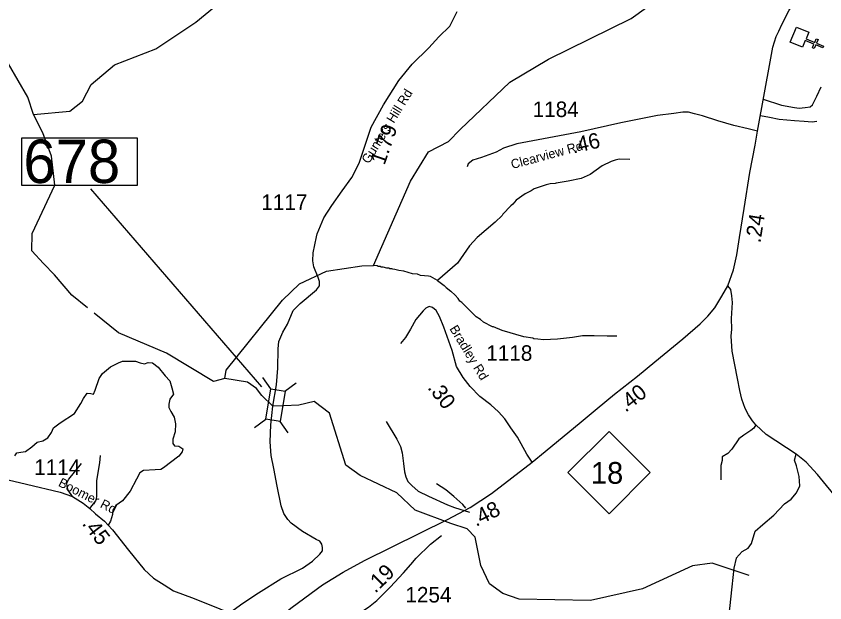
# Model space of a CAD drawing. Extents: x 1248224 to 1454986, y 825081 to 985870.
# Drawn here: x 1331629 to 1338152, y 851342 to 856073 of the extents above; entities that cross this region are included whole.
import ezdxf

# ---------------------------------------------------------------- set-up
doc = ezdxf.new("R2010")
doc.units = 0
for name, color, linetype in [('Exist Cultural Church CELL', 7, 'Continuous'), ('Exist Hydrographic Creek Single Shore', 7, 'Continuous'), ('Exist Hydrographic Misc Water Feature', 7, 'Continuous'), ('Exist Road Non-System Type 51', 7, 'Continuous'), ('Exist Road Primary NC Attributed', 7, 'Continuous'), ('Exist Road Primary NC Mileage Hundredths English Label', 7, 'Continuous'), ('Exist Road Primary NC Shield CELL', 7, 'Continuous'), ('Exist Road Primary NC Shield Number Label', 7, 'Continuous'), ('Exist Road Secondary Mileage Hundredths English Label', 7, 'Continuous'), ('Exist Road Secondary Structure Standard Bridge CELL', 7, 'Continuous'), ('Exist Road Secondary Structure Standard Bridge Number Label', 7, 'Continuous'), ('Exist Road Secondary Type 41 Attributed', 7, 'Continuous'), ('Exist Road Secondary Type 51 Attributed', 7, 'Continuous'), ('Exist Road Secondary Type 51 Label', 7, 'Continuous'), ('Exist Road Secondary Type 51 Number Label', 7, 'Continuous')]:
    doc.layers.add(name, color=color, linetype=linetype)

msp = doc.modelspace()

# ---------------------------------------------------------------- linework, layer by layer
at = {"layer": 'Exist Cultural Church CELL'}
msp.add_lwpolyline([(1338022.6, 855943.8), (1338000.8, 855891.2), (1338071, 855861.8), (1338083.3, 855891.3), (1338098.1, 855885.2), (1338085.7, 855855.7), (1338141.2, 855832.4), (1338135, 855817.7), (1338079.5, 855840.9), (1338067.2, 855811.4), (1338052.5, 855817.5), (1338064.8, 855847), (1337994.6, 855876.4), (1337972.2, 855823.3), (1337874, 855864.4), (1337924.4, 855984.9)], close=True, dxfattribs=at)
at = {"layer": 'Exist Hydrographic Creek Single Shore'}
for points in [[(1333312.1, 853152.1), (1333220, 853127.7), (1332842, 853355.3), (1332454.1, 853520.6), (1332257.2, 853678.9)], [(1333699.8, 852927.7), (1333612.1, 853015.1), (1333569, 853071.4), (1333495.1, 853122.2), (1333312.1, 853152.1)], [(1334034.1, 852966.9), (1333908.1, 852936.6), (1333787.3, 852929.5), (1333699.8, 852927.7)]]:
    msp.add_lwpolyline(points, dxfattribs=at)
at = {"layer": 'Exist Hydrographic Misc Water Feature'}
for points in [[(1331769, 855280.8), (1332062, 855307.7), (1332164, 855387.8), (1332234, 855521), (1332421.1, 855681.4), (1332757, 855809.2), (1333079.1, 856026), (1333334.1, 856237.4), (1333699, 856479.6), (1333857.5, 856585.9), (1333920.1, 856672.1), (1334330, 857438.7), (1334527, 857661.3), (1334901.1, 857991.8), (1335274, 858266.6)], [(1335210.1, 855159.1), (1335612.1, 855541.7), (1335924.1, 855725.8), (1336590.1, 856053.9), (1337048.1, 856386.1), (1337380.1, 856694.5), (1337689, 857473), (1338136.1, 858071.3)], [(1331769, 855280.8), (1331722.3, 855420.3), (1331566.9, 855689), (1331377.3, 855811.9)], [(1332203.5, 853722.1), (1332077.1, 853823.6), (1331938.3, 853987.8), (1331850.1, 854077.7), (1331755.2, 854180.2), (1331757.1, 854319.4), (1331941.8, 854710.4), (1331914.3, 854943), (1331845, 855132.7), (1331769, 855280.8)], [(1333312.1, 853152.1), (1333322.1, 853217.6), (1333778.1, 853782.9), (1333914, 853914.7), (1334133, 854015.4), (1334418.1, 854058.9), (1334512.2, 854061.4), (1334809.1, 854743.7), (1334956.1, 854980.4), (1335117.1, 855062.6), (1335210.1, 855159.1)], [(1336579.7, 854917.1), (1336493.1, 854919.4), (1336461, 854912.2), (1336428.7, 854901), (1336356, 854866.7), (1336258.3, 854797.1), (1336185.6, 854762.8), (1336081, 854741.3), (1335984.7, 854727.6), (1335976.6, 854723.8), (1335936.5, 854720.8), (1335904.3, 854713.5), (1335807.5, 854679.8), (1335783.2, 854664.4), (1335734.6, 854641.6), (1335661.4, 854589.3), (1335636.7, 854557.9), (1335620.4, 854544.3), (1335554.9, 854475.9), (1335548.7, 854466), (1335493.4, 854411.3), (1335346.9, 854288.2), (1335285.8, 854221.9), (1335189, 854080.6), (1335028.4, 853941.4)], [(1335028.4, 853941.4), (1334970.8, 853972.8), (1334954.9, 853977.1), (1334891.1, 853982.7), (1334867.2, 853991.2), (1334827.3, 853996.1), (1334755.8, 854017.8), (1334715.9, 854022.8), (1334684.2, 854031.5), (1334668.2, 854031.9), (1334660.2, 854036), (1334644.2, 854036.4), (1334636.3, 854040.6), (1334620.3, 854041), (1334588.5, 854049.7), (1334572.5, 854050.1), (1334564.6, 854054.3), (1334548.6, 854054.7), (1334540.7, 854058.8), (1334512.2, 854061.4)], [(1335028.4, 853941.4), (1335081.1, 853900.2), (1335096.8, 853883.8), (1335136.2, 853854.9), (1335169.8, 853821.9)], [(1336474.8, 853492.1), (1336396.8, 853492), (1336290.8, 853496.5), (1336196.8, 853494.7), (1336116.5, 853480.6), (1335996.2, 853467.5), (1335884, 853464.2), (1335836.1, 853467.3), (1335804.2, 853472.1), (1335796.3, 853476.2), (1335724.5, 853486), (1335549.7, 853538.1), (1335478.3, 853567.8), (1335470.3, 853568), (1335399.2, 853605.7), (1335375.6, 853626.2), (1335340.1, 853649.1), (1335316.6, 853671.6), (1335285.5, 853700.9), (1335281.6, 853707.9), (1335223.6, 853763.6), (1335208, 853775.9), (1335194.5, 853796.5), (1335169.8, 853821.9)], [(1335136.2, 851982.8), (1334847.1, 852090.5), (1334700.1, 852228), (1334403.1, 852368.5), (1334289.1, 852452.9), (1334157.1, 852872.5), (1334034.1, 852966.9)], [(1337542.1, 851563.6), (1337244.2, 851661.5), (1337085.2, 851641.7), (1336681.1, 851456.2), (1336262.2, 851359.5), (1335687.1, 851371.1), (1335554.1, 851416.4), (1335448.1, 851494.1), (1335376.2, 851643.2), (1335331.2, 851870.7), (1335266.2, 851937.6), (1335136.2, 851982.8)]]:
    msp.add_lwpolyline(points, dxfattribs=at)
at = {"layer": 'Exist Road Non-System Type 51'}
for points in [[(1337655.9, 855404), (1337802.4, 855354.1), (1337906.6, 855337.5), (1337944.3, 855330), (1337992.6, 855336), (1338034.9, 855342.1), (1338053, 855358.7), (1338065.1, 855384.4), (1338089.2, 855426.7), (1338122.5, 855502.2)], [(1337633.3, 855272.6), (1337705.8, 855259), (1337784.3, 855243.8), (1337906.6, 855231.8), (1337985.1, 855227.2), (1338050, 855221.2), (1338089.2, 855225.7)], [(1334912.5, 853696.4), (1334853.4, 853625.6), (1334810, 853549.6), (1334768.5, 853482.7), (1334730.5, 853432.1)], [(1331619.5, 852528.8), (1331635.5, 852550.8), (1331667.5, 852556.8), (1331705.4, 852562.8), (1331755.3, 852600.7), (1331797.3, 852636.7), (1331843.2, 852648.7), (1331885.1, 852672.7), (1331913.1, 852716.6), (1331929.1, 852752.6), (1331985, 852792.6), (1332098.8, 852868.5), (1332150.7, 852950.4), (1332172.7, 852990.4), (1332202.6, 853032.4), (1332232.6, 853030.4), (1332252.6, 853024.4), (1332266.5, 853056.4), (1332298.5, 853152.3), (1332324.4, 853190.2), (1332390.3, 853244.2), (1332454.2, 853278.2), (1332488.2, 853290.2), (1332538.1, 853292.2), (1332592, 853290.2), (1332630, 853276.2), (1332663.9, 853268.2), (1332693.9, 853280.2), (1332729.8, 853278.2), (1332775.8, 853242.2), (1332831.7, 853172.3), (1332867.6, 853132.3), (1332883.6, 853076.3), (1332899.6, 853024.4), (1332867.6, 852984.4), (1332861.6, 852944.4), (1332861.6, 852918.5), (1332875.6, 852884.5), (1332903.6, 852840.5), (1332913.5, 852786.6), (1332911.5, 852720.6), (1332893.6, 852660.7), (1332891.6, 852626.7), (1332905.6, 852608.7), (1332941.5, 852604.7), (1332973.4, 852584.7), (1332967.5, 852558.8), (1332941.5, 852524.8), (1332817.7, 852430.9), (1332795.7, 852416.9), (1332749.8, 852414.9), (1332655.9, 852408.9), (1332625.9, 852389.7), (1332599.9, 852339.8), (1332548, 852243.8), (1332486.1, 852163.9), (1332434.2, 852125.9), (1332410.2, 852090), (1332406.2, 852054), (1332390.3, 852000), (1332372.3, 851968.1)], [(1334612.9, 852804.5), (1334700.7, 852662.6), (1334728.7, 852602.7), (1334742.7, 852550.7), (1334754.6, 852466.8), (1334762.6, 852398.8), (1334772.6, 852356.9), (1334788.6, 852320.9), (1334820.5, 852286.9), (1334872.5, 852242.9), (1334954.3, 852201), (1335108.1, 852131), (1335164, 852111.1), (1335285.3, 852071.9)], [(1337594.6, 852776.9), (1337579.5, 852750.9), (1337556.5, 852733.1), (1337498, 852694.9), (1337459.8, 852664.3), (1337401.3, 852580.3), (1337370.7, 852547.2), (1337324.9, 852519.1), (1337324.9, 852491.1), (1337314.8, 852450.4), (1337314.8, 852333.2)], [(1332222.4, 852103.8), (1332272.4, 852165.8), (1332280.4, 852195.7), (1332280.4, 852245.7), (1332280.4, 852327.6), (1332304.3, 852471.5), (1332310.3, 852531.5)], [(1337436, 851702.7), (1337486.1, 851756.1), (1337532.8, 851782.9), (1337559.5, 851819.6), (1337589.6, 851919.9), (1337653, 851973.3), (1337739.8, 852050.2), (1337826.6, 852140.4), (1337879.8, 852179.3), (1337923.2, 852229.4), (1337949.9, 852286.2), (1337946.6, 852359.7), (1337923.2, 852446.6), (1337906.5, 852493.4), (1337920.1, 852541.9)], [(1332084, 852198.6), (1332048.7, 852249.7), (1332040.7, 852277.7), (1332038.7, 852309.6), (1332052.7, 852339.6), (1332156.6, 852465.5)], [(1335256.7, 852104.6), (1335232.7, 852133.9), (1335160.8, 852199.2), (1335095.6, 852253.8), (1335021, 852301.8)], [(1337436, 851702.7), (1337419.3, 851622.5), (1337402.6, 851472.1), (1337382.6, 851295.1), (1337332.5, 850910.8)]]:
    msp.add_lwpolyline(points, dxfattribs=at)
at = {"layer": 'Exist Road Primary NC Attributed'}
for points in [[(1337610, 855145.1), (1337716.5, 855735.7), (1337733.8, 855822.1), (1337760, 855908.7), (1337780.9, 855952.3), (1337805, 856006), (1337865.7, 856120.5), (1338104.6, 856447.9), (1338581.5, 857121), (1338962.1, 857639.4), (1339074.1, 857803.7), (1339252.1, 858033.9), (1339325.6, 858141.9), (1339512.6, 858365.5)], [(1337370.6, 853897.2), (1337415.9, 854026.8), (1337441.8, 854147.1), (1337463.9, 854288.9), (1337500.9, 854522.2), (1337547.1, 854811.2), (1337591.5, 855031.6), (1337610, 855145.1)], [(1335790.6, 852477.7), (1335895.8, 852561.6), (1336187.6, 852801.6), (1336315.3, 852909), (1336455.9, 853025.7), (1336641, 853170.2), (1336780.9, 853284.3), (1337006.7, 853471.3), (1337147.3, 853591.7), (1337208.4, 853652.8), (1337265.7, 853721.3), (1337321.3, 853813.9), (1337370.6, 853897.2)], [(1333651.5, 851145.2), (1333855.1, 851307.7), (1334101.2, 851487.6), (1334267.2, 851589.2), (1334439.1, 851683.1), (1335108.2, 852014.5), (1335292.7, 852111.3), (1335462.9, 852222.4), (1335790.6, 852477.7)]]:
    msp.add_lwpolyline(points, dxfattribs=at)
at = {"layer": 'Exist Road Primary NC Shield CELL'}
msp.add_lwpolyline([(1336078.6, 852392), (1336411.6, 852725), (1336744.6, 852392), (1336411.6, 852059)], close=True, dxfattribs=at)
at = {"layer": 'Exist Road Secondary Structure Standard Bridge CELL'}
for p, q in [((1333684.1, 853067.4), (1333618, 853159.2)), ((1333795.9, 853049.2), (1333887.7, 853115.4)), ((1333552, 852756.7), (1333643.8, 852822.8)), ((1333824.3, 852712.4), (1333758.1, 852804.2))]:
    msp.add_line(p, q, dxfattribs=at)
msp.add_lwpolyline([(1333643.8, 852822.8), (1333683.6, 853067.5), (1333797.9, 853048.9), (1333758.1, 852804.2)], close=True, dxfattribs=at)
at = {"layer": 'Exist Road Secondary Structure Standard Bridge Number Label'}
msp.add_line((1333611, 853083.1), (1332230.3, 854681.8), dxfattribs=at)
msp.add_lwpolyline([(1331674.9, 855091.9), (1332603.9, 855091.9), (1332603.9, 854707.8), (1331674.9, 854707.8)], close=True, dxfattribs=at)
at = {"layer": 'Exist Road Secondary Type 41 Attributed'}
msp.add_lwpolyline([(1335790.6, 852477.7), (1335749.3, 852539.7), (1335672.2, 852679), (1335618.5, 852754.6), (1335571.5, 852826.7), (1335521.2, 852882.1), (1335459.1, 852937.5), (1335368.6, 853006.4), (1335290.1, 853087.6), (1335234.7, 853159.8), (1335181.1, 853247), (1335145.8, 853376.3), (1335078.7, 853564.3), (1335043.6, 853652.4), (1335016.8, 853699.4), (1334988.3, 853724.6), (1334961.4, 853731.3), (1334932.9, 853717.9), (1334912.5, 853696.4)], dxfattribs=at)
at = {"layer": 'Exist Road Secondary Type 51 Attributed'}
for points in [[(1333699.8, 852927.7), (1333728.5, 853098.8), (1333738.9, 853233.9), (1333741.9, 853390.9), (1333749.2, 853450.1), (1333780.3, 853525.9), (1333818.7, 853589.3), (1333864.4, 853699.4), (1333920.5, 853755.5), (1334052, 853866.1), (1334074.8, 853899.4), (1334076.9, 853932.6), (1334066.5, 853965.8), (1334030.2, 854052.1), (1334021.9, 854099.4), (1334026.1, 854164.8), (1334050.9, 854294.4), (1334056.2, 854316.5), (1334111.2, 854447.8), (1334174.5, 854546.5), (1334259.6, 854665), (1334338.1, 854773.2), (1334397.3, 854888.6), (1334459.6, 855081.8), (1334492.6, 855177.5), (1334593.3, 855359.3), (1334716.8, 855553.6), (1334823.5, 855685), (1334957.4, 855819), (1335039.4, 855905.2), (1335127.4, 855992.9), (1335187.6, 856110.3)], [(1337610, 855145.1), (1337534.9, 855164.9), (1337418.3, 855192.7), (1337288.8, 855227.9), (1337166.6, 855268.6), (1337101.9, 855285.3), (1337053.8, 855298.3), (1337005.6, 855298.3), (1336933.5, 855289), (1336803.9, 855272.3), (1336507.8, 855213.1), (1336183.5, 855140.9), (1335669, 855044.6), (1335559.4, 855007.6), (1335500.1, 854976.5), (1335384.1, 854933.5), (1335311.9, 854911.3), (1335274.9, 854883.5), (1335267.5, 854857.6)], [(1338276.8, 852153.3), (1338093.6, 852377.6), (1338001.1, 852477.3), (1337920.1, 852541.9), (1337680, 852698.6), (1337594.6, 852776.9), (1337569.7, 852810.7), (1337535.9, 852858.8), (1337509.3, 852910.4), (1337482.6, 852983.4), (1337467.5, 853054), (1337447.1, 853151.3), (1337406.2, 853372.1), (1337397.3, 853493.1), (1337401.3, 853549.4), (1337400.8, 853633.7), (1337406.4, 853763.4), (1337402.6, 853818.9), (1337393.7, 853868.7), (1337370.6, 853897.2)], [(1333350.9, 851260.7), (1333456.8, 851339.9), (1333584.4, 851422), (1333765.1, 851534.2), (1333939.4, 851622.9), (1334020, 851679), (1334077.4, 851735), (1334100.6, 851762.4), (1334100.6, 851788.3), (1334093.8, 851815.7), (1334077.4, 851838.9), (1334049.9, 851853.5), (1333939.9, 851916.9), (1333847.9, 851985.2), (1333820, 852013.6), (1333787.8, 852062.5), (1333766, 852124.8), (1333733.8, 852281.7), (1333706.8, 852424), (1333687, 852530.2), (1333678.7, 852639.3), (1333683.9, 852778.5), (1333699.8, 852927.7)], [(1331393.7, 852449.2), (1331442.3, 852396.9), (1331507.4, 852358.5), (1331563.5, 852334.8), (1331711.4, 852297.8), (1331983.5, 852234.2), (1332084, 852198.6), (1332168.3, 852145.4), (1332222.4, 852103.8), (1332270.3, 852061), (1332340.6, 851999.3), (1332372.3, 851968.1), (1332407.1, 851931.2), (1332534.3, 851767), (1332661.4, 851611.6), (1332736.5, 851539.8), (1332823.7, 851486.6), (1332899.1, 851439.2), (1333066.2, 851377.1), (1333271.7, 851294.2), (1333350.9, 851260.7)], [(1334311.5, 851206.7), (1334396.9, 851257.8), (1334470.1, 851307), (1334537.8, 851360.8), (1334646.3, 851468.5), (1334754.8, 851584.5), (1334813.2, 851651.3), (1334856.2, 851701.1), (1334972.3, 851814.3), (1335061.1, 851885.4)]]:
    msp.add_lwpolyline(points, dxfattribs=at)

# ---------------------------------------------------------------- texts
at = {"layer": 'Exist Road Primary NC Mileage Hundredths English Label'}
for s, rotation, p in [('.24', 80.98769, (1337632.4, 854239.5)), ('.40', 37.97608, (1336544.8, 852874.1)), ('.48', 26.35204, (1335338.5, 851953.8))]:
    msp.add_text(s, height=125, rotation=rotation, dxfattribs=at).set_placement(p)
at = {"layer": 'Exist Road Primary NC Shield Number Label'}
msp.add_text('18', height=175, dxfattribs=at).set_placement((1336265.7, 852302.3))
at = {"layer": 'Exist Road Secondary Mileage Hundredths English Label'}
for s, rotation, p in [('1.79', 70.99579, (1334600.1, 854866.3)), ('.46', 12.53629, (1336122.3, 854965)), ('.30', 307.48229, (1334942.8, 853075.6)), ('.45', 307.74581, (1332156, 851979.2)), ('.19', 44.77999, (1334526.4, 851413.8))]:
    msp.add_text(s, height=125, rotation=rotation, dxfattribs=at).set_placement(p)
at = {"layer": 'Exist Road Secondary Structure Standard Bridge Number Label'}
msp.add_text('678', height=350, dxfattribs=at).set_placement((1331687.5, 854727.6))
at = {"layer": 'Exist Road Secondary Type 51 Label'}
for s, rotation, p in [('Gunters Hill Rd', 58.38187, (1334473.8, 854876.9)), ('Clearview Rd', 15.15466, (1335631.3, 854839.8)), ('Bradley Rd', 301.28311, (1335121.9, 853552.9)), ('Boomer Rd', 332.97208, (1331962.9, 852287))]:
    msp.add_text(s, height=75, rotation=rotation, dxfattribs=at).set_placement(p)
at = {"layer": 'Exist Road Secondary Type 51 Number Label'}
for s, p in [('1184', (1335795.3, 855259.7)), ('1117', (1333606.4, 854511.1)), ('1118', (1335421.3, 853294.1)), ('1114', (1331774.4, 852373.2)), ('1254', (1334768.8, 851344.8))]:
    msp.add_text(s, height=125, dxfattribs=at).set_placement(p)

doc.saveas('drawing.dxf')
